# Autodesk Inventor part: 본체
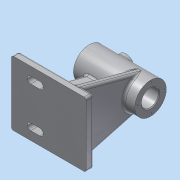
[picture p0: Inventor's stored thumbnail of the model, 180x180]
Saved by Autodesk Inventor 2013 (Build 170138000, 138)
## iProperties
Created: 2019-10
Part Number: 본체
Material: 알루미늄 6061
Document SubType Name: Modeling
Designer: Administrator
Density: 2.71 g/cm^3
Mass: 588.617 g
Surface Area: 540.349 cm^2
Volume: 217.202 cm^3
Author: Administrator
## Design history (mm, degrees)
sketch "스케치1"
  geometry: L1 (0, 0)-(127.136, 0); L2 (0, 14.5)-(0, 21); L3 (0, 21)-(82, 21); L4 (82, 21)-(82, 11.5); L5 (82, 11.5)-(62, 11.5); L6 (62, 11.5)-(62, 14.5); L7 (62, 14.5)-(0, 14.5)
  constraints: 14 end point, 3 perpendicular, 2 parallel, 1 horizontal, 1 vertical alignment
  dimensions: "d0" = 42 diameter of L3 L1; "d2" = 29 diameter of L7 L1; "d3" = 23 diameter of L5 L1; "d4" = 62 distance of L6.end L2.start; "d5" = 82 distance between parallel lines of L4 L2
revolve "회전1" sketch "스케치1" stored, may be unused: angle "d6" = 90 deg
sketch "스케치2"
  geometry: C1 r 11.5 at (0, 0) reference; C2 r 2 at (0, 18)
  constraints: 1 centre point, 1 vertical alignment
  dimensions: "d7" = 18 distance of C1.centre C2.centre
hole "구멍1" sketch "스케치2" at (0, 18) diameter "d8" = 2.459; stored, may be unused: countersink angle "d12" = 82 deg, drill point angle "d14" = 118 deg; dims "d9" = 8, "d10" = 3.023, "d11" = 2, "d13" = 10
node "작업 평면1"
chamfer "모따기1" distance "d18" = 1; stored, may be unused: second distance "d19" = 2, angle "d20" = 45 deg
node "작업 평면2"
sketch "스케치3"
  geometry: C1 r 11 at (-25, 0); 1 further point
  constraints: 1 centre point, 1 horizontal alignment
  dimensions: "d22" = 25 distance of point (0, 0) C1.centre; "d23" = 22 diameter of C1
extrude "돌출1" join sketch "스케치3" stored distance "d24" = 10; taper "d25" = 0 deg
sketch "스케치4"
  geometry: C1 r 11 at (0, 0) reference; C2 r 7 at (0, 0); 1 further point
  constraints: 1 centre point, 1 coincident
  dimensions: "d26" = 14 diameter of C2
extrude "돌출2" cut sketch "스케치4" distance "d28" = 4; taper "d29" = 0 deg
sketch "스케치5"
  geometry: C1 r 7 at (0, 0) reference; C2 r 3.162 at (0, 0); 1 further point
  constraints: 1 centre point, 1 coincident
hole "구멍2" sketch "스케치5" at (0, 0) diameter "d30" = 4.917; stored, may be unused: countersink angle "d34" = 82 deg, drill point angle "d36" = 118 deg; dims "d31" = 8, "d32" = 3.023, "d33" = 2, "d35" = 10
fillet "모깎기1" dims "d37" = 3
node "작업 평면3"
sketch "스케치6"
  geometry: L1 (18, -43)-(-82, -43); L2 (-82, -43)-(-82, 43); L3 (-82, 43)-(18, 43); L4 (18, 43)-(18, -43); L5 (-82, 21)-(-82, -21) reference; 1 further point
  constraints: 8 end point, 2 parallel, 1 horizontal, 1 perpendicular
  dimensions: "d39" = 0 distance between parallel lines of L5 L2; "d40" = 100 distance of L1.start L1.end; "d41" = 86 distance of L1.end L2.end; "d42" = 43 distance from line of L1 point (0, 0)
extrude "돌출3" join sketch "스케치6" distance "d43" = 10; taper "d44" = 0 deg
fillet "모깎기2" dims "d45" = 3
sketch "스케치7"
  geometry: L1 (8, 31.5)-(20, 31.5); L2 (8, 22.5)-(20, 22.5); L3 (8, 34)-(20, 34); L4 (8, 20)-(20, 20); L5 (-18, 40)-(-18, -40) reference; A1 r 4.5 centre (8, 27) between (8, 31.5) and (8, 22.5); A2 r 4.5 centre (20, 27) between (20, 22.5) and (20, 31.5); A3 r 7 centre (20, 27) between (20, 20) and (20, 34); A4 r 7 centre (8, 27) between (8, 34) and (8, 20); 1 further point
  constraints: 8 end point, 8 point on circle, 8 tangent, 4 centre point, 2 coincident, 2 equal radius, 1 horizontal alignment
  dimensions: "d46" = 9 diameter of A1; "d49" = 27 vertical distance of A1.centre point (0, 0); "d50" = 12 distance of A2.centre A1.centre; "d51" = 14 diameter of A4; "d52" = 26 distance from line of L5 A1.centre
extrude "돌출4" join sketch "스케치7" distance "d53" = 3; taper "d54" = 0 deg
node "작업 평면4"
fillet "모깎기3" dims "d55" = 3
sketch "스케치8"
  geometry: L1 (20, 31.5)-(8, 31.5) reference; L2 (8, 22.5)-(20, 22.5) reference; L3 (20, -22.5)-(8, -22.5) reference; L4 (8, -31.5)-(20, -31.5) reference; A1 r 4.5 centre (8, 27) between (8, 31.5) and (8, 22.5) reference; A2 r 4.5 centre (20, 27) between (20, 22.5) and (20, 31.5) reference; A3 r 4.5 centre (8, -27) between (8, -22.5) and (8, -31.5) reference; A4 r 4.5 centre (20, -27) between (20, -31.5) and (20, -22.5) reference; 1 further point
extrude "돌출5" cut sketch "스케치8" stored distance "d56" = 3; taper "d57" = 0 deg
node "작업 평면5"
sketch "스케치9"
  geometry: L1 (-76, 40)-(-76, -40) reference; L2 (-79, -43)-(-86, -43) reference; L3 (-86, -43)-(-86, 43) reference; L4 (-86, 43)-(-79, 43) reference; L5 (-78.217, -42.896)-(5.48, -20.272); L6 (-78.217, 42.896)-(5.48, 20.272); L7 (-76, 40)-(-76, -40); C1 r 14.5 at (0, 0) reference; C2 r 11.5 at (0, 0) reference; A1 r 3 centre (-79, -40) between (-79, -43) and (-76, -40) reference; A2 r 3 centre (-79, 40) between (-76, 40) and (-79, 43) reference; A3 r 3 centre (-79, 40) between (-76, 40) and (-79, 43) reference; A4 r 3 centre (-79, -40) between (-79, -43) and (-76, -40) reference; A5 r 21 centre (0, 0) between (5.48, 20.272) and (5.48, -20.272) reference; A6 r 21 centre (0, 0) between (5.48, 20.272) and (5.48, -20.272); A7 r 3 centre (-79, 40) between (-76, 40) and (-78.217, 42.896); A8 r 3 centre (-79, -40) between (-79, -43) and (-76, -40); 2 further points
  constraints: 15 tangent, 10 point on circle, 6 end point, 3 centre point, 1 collinear, 2 other
extrude "돌출6" join sketch "스케치9" stored distance "d59" = 10; taper "d60" = 0 deg
fillet "모깎기4" dims "d61" = 3
node "작업 평면6"
sketch "스케치10"
  geometry: L1 (0, 10)-(69.208, 10) reference; L2 (15, 65)-(97, 65) reference; L3 (12, 10)-(32.018, 65); L4 (-3, 0)-(-3, 7) reference; 1 further point
  constraints: 2 end point, 2 point on line
  dimensions: "d62" = 15 distance from line of L4 L3.start; "d63" = 70 deg angle of L1 L3
feature "리브1" sketch "스케치10" dims "d64" = 1, "d65" = 10, "d66" = 0, "d67" = 0, "d68" = 1, "d69" = 1
fillet "모깎기5" dims "d70" = 3
sketch "스케치11"
  geometry: L1 (-15, -43)-(79, -43) reference; L2 (82, -40)-(82, 40) reference; 2 further points
  constraints: 1 other
  dimensions: "d71" = 43 distance from line of L1 point (75, 0); "d72" = 7 distance from line of L2 point (75, 0)
extrude "돌출7" join sketch "스케치11" distance "d73" = 0.5; taper "d74" = 0 deg
node "솔리드1"
pattern_circular "원형 패턴1" dims angle "d16" = 360 deg
mirror "대칭1"
mirror "대칭2"
node "절단 모서리 투영1"
other parameters: "d21" = 24, "d38" = -86, "d58" = 62
